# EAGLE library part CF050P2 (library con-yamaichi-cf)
Compact Flash Card Reader, Type I and II CF 050 P2 - * 03 - * 0 - DS
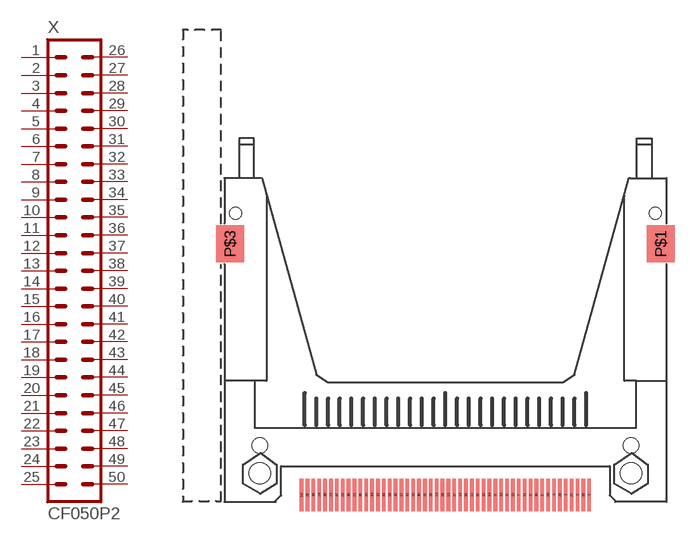
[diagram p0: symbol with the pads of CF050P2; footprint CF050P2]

Designator prefix X

## CF050P2  [CF050P2]
1  1  pas
2  2  pas
3  3  pas
4  4  pas
5  5  pas
6  6  pas
7  7  pas
8  8  pas
9  9  pas
10  10  pas
11  11  pas
12  12  pas
13  13  pas
14  14  pas
15  15  pas
16  16  pas
17  17  pas
18  18  pas
19  19  pas
20  20  pas
21  21  pas
22  22  pas
23  23  pas
24  24  pas
25  25  pas
26  26  pas
27  27  pas
28  28  pas
29  29  pas
30  30  pas
31  31  pas
32  32  pas
33  33  pas
34  34  pas
35  35  pas
36  36  pas
37  37  pas
38  38  pas
39  39  pas
40  40  pas
41  41  pas
42  42  pas
43  43  pas
44  44  pas
45  45  pas
46  46  pas
47  47  pas
48  48  pas
49  49  pas
50  50  pas

## Footprint CF050P2 (pad centres in mm)
CF 050 P2 - * 03 - * 0 - DS Compact Flash Card Reader, Type I and II Yamaichi Electronics Cadded by Lutz Lisseck, Jan. 2003
smd 0.4 x 3.5: 1 15.557,-5.35; 2 14.287,-5.35; 3 13.018,-5.35; 4 11.748,-5.35; 5 10.477,-5.35; 6 9.207,-5.35; 7 7.938,-5.35; 8 6.668,-5.35; 9 5.397,-5.35; 10 4.128,-5.35; 11 2.857,-5.35; 12 1.587,-5.35; 13 0.318,-5.35; 14 -0.953,-5.35; 15 -2.223,-5.35; 16 -3.493,-5.35; 17 -4.763,-5.35; 18 -6.032,-5.35; 19 -7.303,-5.35; 20 -8.572,-5.35; 21 -9.842,-5.35; 22 -11.113,-5.35; 23 -12.383,-5.35; 24 -13.652,-5.35; 25 -14.922,-5.35; 26 14.922,-5.35; 27 13.652,-5.35; 28 12.383,-5.35; 29 11.113,-5.35; 30 9.842,-5.35; 31 8.572,-5.35; 32 7.303,-5.35; 33 6.032,-5.35; 34 4.763,-5.35; 35 3.493,-5.35; 36 2.223,-5.35; 37 0.953,-5.35; 38 -0.318,-5.35; 39 -1.587,-5.35; 40 -2.857,-5.35; 41 -4.128,-5.35; 42 -5.397,-5.35; 43 -6.668,-5.35; 44 -7.938,-5.35; 45 -9.207,-5.35; 46 -10.477,-5.35; 47 -11.748,-5.35; 48 -13.018,-5.35; 49 -14.287,-5.35; 50 -15.557,-5.35
smd 3 x 4: P$1 23.3,21.8; P$3 -23.3,21.8
hole 1.7 at -20.08,0
hole 2.3 at -20.08,-3
hole 2.3 at 20.08,-3
hole 1.7 at 20.08,0
hole 1.3 at 22.7,25.1
hole 1.3 at -22.7,25.1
